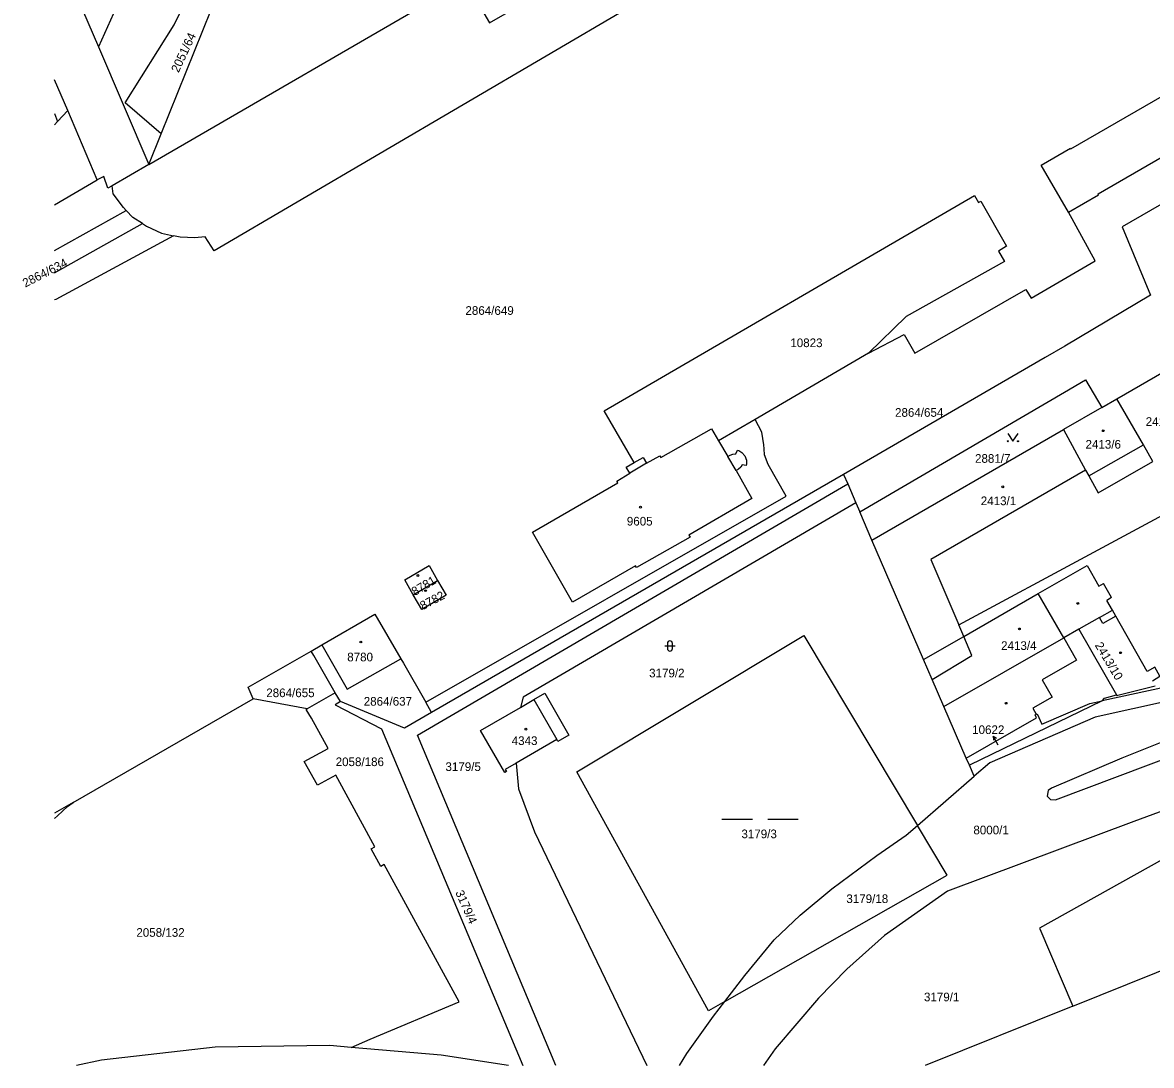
# Model space of a CAD drawing. Extents: x -564952 to -564307, y -1202373 to -1201847.
# Drawn here: x -564951.7 to -564730.1, y -1202361.7 to -1202157.1 of the extents above; entities that cross this region are included whole.
import ezdxf

# ---------------------------------------------------------------- set-up
doc = ezdxf.new("R2010")
doc.units = 0
for name, color, linetype in [('Hranice parcel', 7, 'Continuous'), ('Parcelní čísla', 7, 'Continuous'), ('Pop  PČ popisy', 7, 'Continuous'), ('Vnitřní kresba', 7, 'Continuous'), ('Značky budov', 7, 'Continuous'), ('Značky kultur', 7, 'Continuous')]:
    doc.layers.add(name, color=color, linetype=linetype)

msp = doc.modelspace()

# ---------------------------------------------------------------- linework, layer by layer
at = {"layer": 'Hranice parcel'}
for p, q in [((-564945.44, -1202141.72), (-564936.81, -1202161.87)), ((-564933.25, -1202153.98), (-564936.81, -1202161.87)), ((-564936.81, -1202161.87), (-564926.94, -1202184.91)), ((-564942.83, -1202174.34), (-564945.44, -1202168.3)), ((-564942.83, -1202174.34), (-564944.83, -1202176.48)), ((-564937.08, -1202187.94), (-564942.83, -1202174.34)), ((-564945.44, -1202174.95), (-564944.83, -1202176.48)), ((-564944.83, -1202176.48), (-564945.44, -1202177.12)), ((-564926.94, -1202184.91), (-564924.52, -1202178.92)), ((-564926.94, -1202184.91), (-564934.13, -1202189.1)), ((-564945.44, -1202192.81), (-564937.08, -1202187.94)), ((-564934.13, -1202189.1), (-564934.98, -1202189.58)), ((-564945.44, -1202201.78), (-564931.38, -1202193.94)), ((-564945.44, -1202206.19), (-564928.2, -1202196.52)), ((-564785.7, -1202221.92), (-564807.9, -1202234.94)), ((-564736.94, -1202230.91), (-564726.37, -1202224.82)), ((-564743.06, -1202227.18), (-564739.89, -1202232.61)), ((-564739.89, -1202232.61), (-564736.94, -1202230.91)), ((-564739.89, -1202232.61), (-564747.41, -1202236.95)), ((-564816.5, -1202236.77), (-564815.1, -1202239.16)), ((-564807.9, -1202234.94), (-564815.1, -1202239.16)), ((-564785, -1202258.61), (-564747.41, -1202236.95)), ((-564815.1, -1202239.16), (-564813.31, -1202242.2)), ((-564833.24, -1202244.33), (-564831.68, -1202243.42)), ((-564831.68, -1202243.42), (-564829.93, -1202242.39)), ((-564790.56, -1202245.73), (-564871.42, -1202292.43)), ((-564790.56, -1202245.73), (-564789.76, -1202247.58)), ((-564789.76, -1202247.58), (-564788.15, -1202251.31)), ((-564788.15, -1202251.31), (-564787.4, -1202253.06)), ((-564785, -1202258.61), (-564787.4, -1202253.06)), ((-564875.03, -1202269.34), (-564870.24, -1202266.54)), ((-564895.04, -1202280.4), (-564892.97, -1202279.17)), ((-564736.97, -1202289.12), (-564729.4, -1202287.2)), ((-564941.79, -1202310.12), (-564906.46, -1202289.77)), ((-564895.83, -1202291.75), (-564906.46, -1202289.77)), ((-564890.34, -1202288.6), (-564895.83, -1202291.75)), ((-564889.32, -1202290.32), (-564890.34, -1202288.6)), ((-564737.03, -1202289.01), (-564736.97, -1202289.12)), ((-564876.74, -1202295.5), (-564889.32, -1202290.32)), ((-564871.42, -1202292.43), (-564872.57, -1202290.42)), ((-564739.83, -1202290.15), (-564765.86, -1202302.81)), ((-564742.24, -1202290.67), (-564739.83, -1202290.15)), ((-564871.42, -1202292.43), (-564876.74, -1202295.5)), ((-564881.28, -1202295.63), (-564853.5, -1202361.7)), ((-564854.85, -1202302.38), (-564854.4, -1202307.42)), ((-564765.86, -1202302.81), (-564766.49, -1202301.38)), ((-564764.92, -1202304.97), (-564765.86, -1202302.81)), ((-564761.86, -1202302.33), (-564764.92, -1202304.97)), ((-564694.22, -1202302.43), (-564752.14, -1202334.76)), ((-564776.08, -1202314.61), (-564764.92, -1202304.97)), ((-564941.79, -1202310.12), (-564945.44, -1202312.22)), ((-564745.54, -1202350.05), (-564774.57, -1202361.7))]:
    msp.add_line(p, q, dxfattribs=at)
for points in [[(-564924.52, -1202178.92), (-564931.57, -1202172.85), (-564921.97, -1202157.55), (-564916.7, -1202146.84), (-564913.21, -1202138.56), (-564907.66, -1202121.45), (-564904.96, -1202106.77), (-564903.67, -1202088.86), (-564904.13, -1202073.93), (-564905.44, -1202062.02), (-564907.33, -1202053.49)], [(-564924.52, -1202178.92), (-564906.52, -1202134.25), (-564904.95, -1202126.35), (-564902.2, -1202105), (-564902.61, -1202078.89), (-564904.65, -1202060.96)], [(-564926.94, -1202184.91), (-564864.85, -1202148.86), (-564860.04, -1202157.15), (-564850.27, -1202151.47), (-564855.08, -1202143.19), (-564844.6, -1202137.1), (-564832.72, -1202130.27)], [(-564816.39, -1202144.49), (-564914.12, -1202201.86), (-564915.88, -1202199.13), (-564917.88, -1202199.31), (-564920.81, -1202199.2), (-564922.12, -1202198.9)], [(-564746.42, -1202194.29), (-564751.8, -1202185.07), (-564746.02, -1202181.72), (-564745.95, -1202181.85), (-564713.53, -1202163.13), (-564713.63, -1202162.96), (-564707.79, -1202159.58)], [(-564746.42, -1202194.29), (-564740.54, -1202190.88), (-564740.63, -1202190.71), (-564708.37, -1202172.01), (-564708.29, -1202172.15), (-564702.44, -1202168.76), (-564702.76, -1202168.23)], [(-564694.35, -1202173.24), (-564735.89, -1202197.13), (-564730.32, -1202210.59), (-564747.11, -1202220.56)], [(-564934.98, -1202189.58), (-564935.74, -1202187.28), (-564937.08, -1202187.94)], [(-564931.38, -1202193.94), (-564931.92, -1202193.39), (-564933.95, -1202190.68), (-564934.13, -1202189.1)], [(-564831.68, -1202243.42), (-564837.59, -1202233.25), (-564764.9, -1202191.01)], [(-564764.9, -1202191.01), (-564764.1, -1202192.39), (-564763.65, -1202192.14), (-564758.56, -1202200.97)], [(-564928.2, -1202196.52), (-564930.04, -1202195.33), (-564931.38, -1202193.94)], [(-564785.7, -1202221.92), (-564778.69, -1202218.27), (-564776.57, -1202221.95), (-564754.81, -1202209.44), (-564753.72, -1202211.14), (-564741.21, -1202203.85), (-564746.42, -1202194.29)], [(-564928.2, -1202196.52), (-564927.39, -1202197.04), (-564924.46, -1202198.37), (-564922.12, -1202198.9)], [(-564922.12, -1202198.9), (-564945.2, -1202211.4), (-564945.44, -1202211.51)], [(-564758.56, -1202200.97), (-564760.17, -1202201.9), (-564759.01, -1202203.96)], [(-564759.01, -1202203.96), (-564778.26, -1202214.73), (-564785.7, -1202221.92)], [(-564747.11, -1202220.56), (-564751, -1202222.81), (-564790.56, -1202245.73)], [(-564787.4, -1202253.06), (-564747.21, -1202229.6), (-564743.06, -1202227.18)], [(-564729.85, -1202243.2), (-564731.7, -1202239.94), (-564736.94, -1202230.91)], [(-564872.57, -1202290.42), (-564801.86, -1202250.02), (-564805.4, -1202243.79), (-564806.09, -1202241.91), (-564806.15, -1202240.7), (-564806.19, -1202239.92), (-564806.59, -1202237.44), (-564807.9, -1202234.94)], [(-564829.93, -1202242.39), (-564829.26, -1202243.56), (-564826.64, -1202242.1), (-564826.44, -1202242.45), (-564816.5, -1202236.77)], [(-564747.41, -1202236.95), (-564743.07, -1202244.93), (-564742.44, -1202246.04), (-564740.58, -1202249.32), (-564729.85, -1202243.2)], [(-564813.31, -1202242.2), (-564812.84, -1202241.95), (-564812.28, -1202241.76), (-564811.71, -1202241.73), (-564811.42, -1202241.01), (-564811.15, -1202241.07), (-564810.57, -1202241.45), (-564809.98, -1202242.11), (-564809.61, -1202242.97), (-564809.64, -1202243.75), (-564809.68, -1202244), (-564810.47, -1202243.85), (-564810.73, -1202244.3), (-564811.19, -1202244.73), (-564811.67, -1202244.99), (-564808.58, -1202250.48), (-564820.92, -1202257.67), (-564820.71, -1202258.02), (-564831.19, -1202264.03), (-564831.38, -1202263.7), (-564843.75, -1202270.82), (-564851.62, -1202257.05), (-564834.87, -1202247.38), (-564835.07, -1202247.04), (-564832.53, -1202245.49), (-564833.24, -1202244.33)], [(-564847.07, -1202361.7), (-564874.18, -1202296.89), (-564790.98, -1202248.29), (-564789.76, -1202247.58)], [(-564773.2, -1202285.97), (-564765.4, -1202281.28), (-564766.99, -1202277.53), (-564767.95, -1202275.27), (-564714.94, -1202246.71)], [(-564788.15, -1202251.31), (-564853.46, -1202289.46), (-564854, -1202291.44)], [(-564773.2, -1202285.97), (-564774.89, -1202282.05), (-564785, -1202258.61)], [(-564875.03, -1202269.34), (-564876.7, -1202266.45), (-564871.93, -1202263.64), (-564870.24, -1202266.54)], [(-564870.24, -1202266.54), (-564868.56, -1202269.43), (-564873.36, -1202272.23), (-564875.03, -1202269.34)], [(-564892.97, -1202279.17), (-564882.55, -1202273.19), (-564877.45, -1202281.93)], [(-564730.99, -1202284.39), (-564737.14, -1202273.55), (-564739.68, -1202275), (-564740.36, -1202273.82), (-564744.39, -1202276.13), (-564737.03, -1202289.01)], [(-564813.86, -1202349.15), (-564817.1, -1202350.99), (-564842.91, -1202304.11), (-564798.35, -1202277.35), (-564776.08, -1202314.61)], [(-564906.46, -1202289.77), (-564907.41, -1202287.48), (-564895.04, -1202280.4)], [(-564890.34, -1202288.6), (-564894.54, -1202281.27), (-564895.04, -1202280.4)], [(-564892.97, -1202279.17), (-564887.97, -1202287.89), (-564877.45, -1202281.93)], [(-564700.71, -1202280.36), (-564701.49, -1202280.66), (-564726.39, -1202290.11), (-564741.18, -1202293.34), (-564761.86, -1202302.33)], [(-564708.6, -1202280.36), (-564727.36, -1202287.47), (-564739.83, -1202290.15)], [(-564877.45, -1202281.93), (-564876.97, -1202282.77), (-564872.57, -1202290.42)], [(-564729.95, -1202286.22), (-564728.47, -1202285.32), (-564729.49, -1202283.53), (-564730.99, -1202284.39)], [(-564766.49, -1202301.38), (-564770.9, -1202291.29), (-564773.2, -1202285.97)], [(-564699.37, -1202287.29), (-564703.08, -1202288.68), (-564707.03, -1202290.18), (-564723.83, -1202296.58), (-564735.98, -1202301.38), (-564749.78, -1202307.33), (-564750.4, -1202307.73), (-564750.6, -1202308.84), (-564749.96, -1202309.55), (-564748.95, -1202309.62), (-564705.88, -1202293.37), (-564701.95, -1202291.87), (-564698.32, -1202290.49), (-564697.69, -1202289.96), (-564697.33, -1202289.21), (-564697.44, -1202288.16), (-564698.24, -1202287.35), (-564699.37, -1202287.29)], [(-564854, -1202291.44), (-564851.39, -1202289.93), (-564849.22, -1202288.68), (-564844.47, -1202296.91), (-564846.63, -1202298.17), (-564846.87, -1202297.76), (-564854.85, -1202302.38)], [(-564739.83, -1202290.15), (-564739.35, -1202289.67), (-564737.03, -1202289.01)], [(-564887.24, -1202358.17), (-564883.46, -1202356.57), (-564866.04, -1202349.2), (-564880.72, -1202322.26), (-564881.42, -1202322.68), (-564883.32, -1202319.19), (-564882.59, -1202318.79), (-564890.23, -1202304.76), (-564893.8, -1202306.73), (-564896.41, -1202302.05), (-564891.72, -1202299.51), (-564895.01, -1202293.55), (-564896.02, -1202291.86), (-564895.83, -1202291.75)], [(-564889.32, -1202290.32), (-564890.38, -1202290.93), (-564881.28, -1202295.63)], [(-564854.85, -1202302.38), (-564856.99, -1202303.61), (-564856.76, -1202304.03), (-564857.08, -1202304.21), (-564861.84, -1202295.97), (-564854, -1202291.44)], [(-564752.56, -1202292.73), (-564751.63, -1202294.76), (-564742.24, -1202290.67)], [(-564766.49, -1202301.38), (-564752.73, -1202293.48), (-564752.99, -1202292.92), (-564752.75, -1202292.81), (-564752.56, -1202292.73)], [(-564695.22, -1202298.06), (-564708.2, -1202304.48), (-564733.57, -1202313.86), (-564770.15, -1202327.48), (-564782.51, -1202336.22), (-564789.91, -1202342.84), (-564795.49, -1202348.48), (-564803.99, -1202358.45)], [(-564854.4, -1202307.42), (-564851.24, -1202315.85), (-564829.16, -1202361.7)], [(-564945.44, -1202313.27), (-564944.87, -1202312.72), (-564942.9, -1202310.91), (-564941.79, -1202310.12)], [(-564813.86, -1202349.15), (-564809.95, -1202344.07), (-564804.17, -1202337.07), (-564799.11, -1202332.23), (-564792.85, -1202327.06), (-564784.05, -1202320.5), (-564778.26, -1202316.49), (-564776.08, -1202314.61)], [(-564813.86, -1202349.15), (-564770.26, -1202324.35), (-564776.08, -1202314.61)], [(-564745.54, -1202350.05), (-564696.61, -1202330.41), (-564691.72, -1202327.95), (-564688.9, -1202325.03)], [(-564752.14, -1202334.76), (-564752.07, -1202334.93), (-564745.54, -1202350.05)], [(-564822.78, -1202361.7), (-564821.35, -1202359.35), (-564816.09, -1202352.05), (-564813.86, -1202349.15)], [(-564887.24, -1202358.17), (-564891.4, -1202357.82), (-564913.93, -1202358.13), (-564936.22, -1202360.65), (-564941.11, -1202361.7)], [(-564856.31, -1202361.7), (-564869.56, -1202359.66), (-564887.24, -1202358.17)], [(-564803.99, -1202358.45), (-564806.26, -1202361.7)]]:
    msp.add_lwpolyline(points, dxfattribs=at)
at = {"layer": 'Pop  PČ popisy'}
for p, q in [((-564760.2, -1202298.84), (-564761.2, -1202297.1)), ((-564761.2, -1202297.1), (-564760.58, -1202297.51)), ((-564761.2, -1202297.1), (-564761.16, -1202297.85))]:
    msp.add_line(p, q, dxfattribs=at)
at = {"layer": 'Vnitřní kresba'}
for p, q in [((-564742.44, -1202246.04), (-564731.7, -1202239.94)), ((-564811.67, -1202244.99), (-564813.31, -1202242.2)), ((-564829.26, -1202243.56), (-564832.53, -1202245.49)), ((-564743.07, -1202244.93), (-564773.46, -1202262.4)), ((-564773.46, -1202262.4), (-564767.95, -1202275.27)), ((-564752.37, -1202269.12), (-564742.78, -1202263.6)), ((-564742.78, -1202263.6), (-564740.49, -1202267.64)), ((-564740.49, -1202267.64), (-564739.54, -1202267.11)), ((-564737.95, -1202269.91), (-564739.54, -1202267.11)), ((-564766.99, -1202277.53), (-564752.37, -1202269.12)), ((-564747.36, -1202277.83), (-564752.37, -1202269.12)), ((-564737.95, -1202269.91), (-564738.9, -1202270.45)), ((-564737.81, -1202272.36), (-564738.9, -1202270.45)), ((-564740.36, -1202273.82), (-564737.81, -1202272.36)), ((-564737.14, -1202273.55), (-564737.81, -1202272.36)), ((-564744.39, -1202276.13), (-564747.36, -1202277.83)), ((-564774.89, -1202282.05), (-564766.99, -1202277.53)), ((-564770.9, -1202291.29), (-564747.36, -1202277.83)), ((-564747.36, -1202277.83), (-564744.87, -1202282.17)), ((-564744.87, -1202282.17), (-564751.59, -1202286.03)), ((-564751.59, -1202286.03), (-564749.64, -1202289.43)), ((-564851.39, -1202289.93), (-564846.87, -1202297.76)), ((-564749.64, -1202289.43), (-564753.44, -1202291.61)), ((-564753.44, -1202291.61), (-564752.75, -1202292.81))]:
    msp.add_line(p, q, dxfattribs=at)
at = {"layer": 'Značky budov'}
for centre in [(-564739.6, -1202237.16), (-564759.33, -1202248.17), (-564830.43, -1202252.16), (-564874.12, -1202265.56), (-564872.62, -1202268.55), (-564744.59, -1202271.04), (-564756.06, -1202276.06), (-564885.31, -1202278.62), (-564736.2, -1202280.73), (-564758.67, -1202290.64), (-564852.91, -1202295.73)]:
    msp.add_circle(centre, 0.175, dxfattribs=at)
at = {"layer": 'Značky kultur'}
for p, q in [((-564825.65, -1202279.4), (-564823.65, -1202279.4)), ((-564825.15, -1202278.9), (-564825.15, -1202279.9)), ((-564824.15, -1202279.9), (-564824.15, -1202278.9)), ((-564814.46, -1202313.39), (-564808.46, -1202313.39)), ((-564805.46, -1202313.39), (-564799.46, -1202313.39))]:
    msp.add_line(p, q, dxfattribs=at)
msp.add_lwpolyline([(-564758.33, -1202237.72), (-564757.33, -1202239.22), (-564756.33, -1202237.72)], dxfattribs=at)
for centre in [(-564758.33, -1202239.22), (-564756.33, -1202239.22)]:
    msp.add_circle(centre, 0.1, dxfattribs=at)
for centre, start, end in [((-564824.65, -1202278.9), 0, 180), ((-564824.65, -1202279.9), 180, 359.9879)]:
    msp.add_arc(centre, 0.5, start, end, dxfattribs=at)

# ---------------------------------------------------------------- texts
at = {"layer": 'Parcelní čísla'}
for s, rotation, p in [('2051/64', 65, (-564921.1, -1202167.03)), ('2864/634', 27, (-564951.17, -1202209.08)), ('8781', 31, (-564874.73, -1202269.62)), ('8782', 28, (-564873.15, -1202272.39)), ('2413/10', 301, (-564741.32, -1202279.25)), ('3179/4', 294, (-564866.81, -1202327.76))]:
    msp.add_text(s, height=1.7, rotation=rotation, dxfattribs=at).set_placement(p)
for s, p in [('2864/649', (-564864.79, -1202214.43)), ('10823', (-564801.02, -1202220.76)), ('2864/654', (-564780.47, -1202234.43)), ('2413/2', (-564731.27, -1202236.22)), ('2413/6', (-564743.08, -1202240.68)), ('2881/7', (-564764.77, -1202243.46)), ('2413/1', (-564763.64, -1202251.77)), ('9605', (-564833.11, -1202255.77)), ('2413/4', (-564759.65, -1202280.18)), ('8780', (-564887.99, -1202282.42)), ('3179/2', (-564828.73, -1202285.56)), ('2864/655', (-564903.88, -1202289.44)), ('2864/637', (-564884.75, -1202291.11)), ('10622', (-564765.33, -1202296.68)), ('4343', (-564855.71, -1202298.83)), ('2058/186', (-564890.26, -1202302.97)), ('3179/5', (-564868.71, -1202303.93)), ('3179/3', (-564810.62, -1202317.12)), ('8000/1', (-564765.09, -1202316.36)), ('3179/18', (-564790.02, -1202329.84)), ('2058/132', (-564929.38, -1202336.46)), ('3179/1', (-564774.79, -1202349.12))]:
    msp.add_text(s, height=1.7, dxfattribs=at).set_placement(p)

doc.saveas('drawing.dxf')
